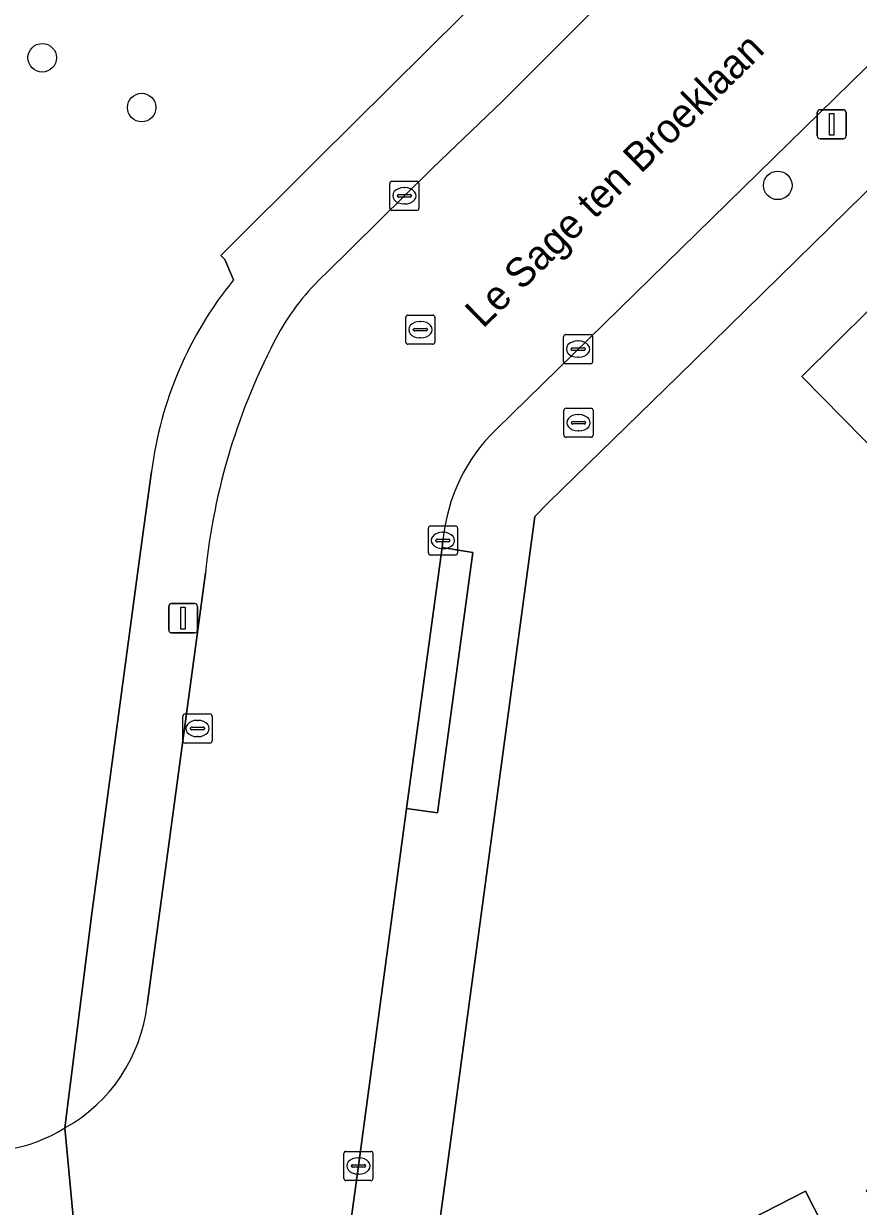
# Model space of a CAD drawing. Extents: x 161402 to 161933, y 381647 to 382315.
# Drawn here: x 161759.22 to 161787.85, y 382075.91 to 382116.47 of the extents above; entities that cross this region are included whole.
import ezdxf

# ---------------------------------------------------------------- set-up
doc = ezdxf.new("R2010")
doc.units = 0
for name, color, linetype in [('IMGEO_Boom', 7, 'Continuous'), ('IMGEO_Brandkraan', 7, 'Continuous'), ('IMGEO_Erf', 7, 'Continuous'), ('IMGEO_Groenvoorziening', 7, 'Continuous'), ('IMGEO_Kolk', 7, 'Continuous'), ('IMGEO_Lichtmast', 7, 'Continuous'), ('IMGEO_Muur', 7, 'Continuous'), ('IMGEO_Openbare_ruimte_label', 7, 'Continuous'), ('IMGEO_Pand', 7, 'Continuous'), ('IMGEO_Rijbaan_lokaal_gesloten', 7, 'Continuous'), ('IMGEO_Rioolput', 7, 'Continuous'), ('IMGEO_Voetpad_open', 7, 'Continuous')]:
    doc.layers.add(name, color=color, linetype=linetype)

msp = doc.modelspace()

# ---------------------------------------------------------------- linework, layer by layer
at = {"layer": 'IMGEO_Boom'}
for centre in [(161759.861, 382115.302), (161763.272, 382113.595), (161785.089, 382110.925)]:
    msp.add_circle(centre, 0.489, dxfattribs=at)
at = {"layer": 'IMGEO_Brandkraan'}
for p, q in [((161777.831, 382103.284), (161778.683, 382103.284)), ((161777.756, 382102.358), (161777.756, 382103.21)), ((161778.244, 382103.064), (161778.269, 382103.064)), ((161778.757, 382103.21), (161778.757, 382102.358)), ((161778.015, 382102.778), (161778.015, 382102.79)), ((161778.453, 382102.741), (161778.055, 382102.741)), ((161778.058, 382102.827), (161778.456, 382102.827)), ((161778.267, 382102.504), (161778.242, 382102.504)), ((161778.499, 382102.79), (161778.499, 382102.778)), ((161778.683, 382102.284), (161777.831, 382102.284))]:
    msp.add_line(p, q, dxfattribs=at)
for points in [[(161777.831, 382103.284), (161778.683, 382103.284)], [(161777.756, 382102.358), (161777.756, 382103.21)], [(161778.757, 382103.21), (161778.757, 382102.358)], [(161778.683, 382102.284), (161777.831, 382102.284)]]:
    msp.add_lwpolyline(points, dxfattribs=at)
for centre, radius, start, end in [((161777.833, 382103.208), 0.0765, 91.552, 178.448), ((161777.833, 382103.208), 0.0765, 91.552, 178.448), ((161778.681, 382103.208), 0.0765, 1.552, 88.448), ((161778.681, 382103.208), 0.0765, 1.552, 88.448), ((161778.055, 382102.787), 0.0403, 85.8775, 175.7526), ((161778.052, 382102.777), 0.0366, 178.938, 274.7102), ((161778.456, 382102.784), 0.043, 264.8664, 352.4533), ((161778.46, 382102.789), 0.0386, 1.7309, 96.639), ((161777.833, 382102.36), 0.0765, 181.552, 268.448), ((161777.833, 382102.36), 0.0765, 181.552, 268.448), ((161778.681, 382102.36), 0.0765, 271.552, 358.448), ((161778.681, 382102.36), 0.0765, 271.552, 358.448)]:
    msp.add_arc(centre, radius, start, end, dxfattribs=at)
for centre, major_axis, ratio, start_param, end_param in [((161778.243, 382102.784), (-0.387, 0.002), 0.722429, 4.712389, 7.853982), ((161778.268, 382102.784), (-0.39, 0.002), 0.717154, 1.570796, 4.712389)]:
    msp.add_ellipse(centre, major_axis=major_axis, ratio=ratio, start_param=start_param, end_param=end_param, dxfattribs=at)
at = {"layer": 'IMGEO_Erf'}
for points in [[(161804.249, 382126.529), (161781.67, 382104.382), (161777.238, 382100.058), (161776.756, 382099.569), (161773.703, 382076.916), (161762.821, 381997.456)], [(161789.417, 382100.81), (161785.909, 382104.373), (161789.402, 382107.818)], [(161783.505, 382056.018), (161783.263, 382058.701), (161776.645, 382071.618), (161786.037, 382076.43), (161787.222, 382074.116), (161788.878, 382075.604), (161788.117, 382076.444), (161788.484, 382076.777), (161796.387, 382068.043), (161796.339, 382068), (161797.532, 382065.679), (161799.064, 382066.435), (161805.902, 382053.086)]]:
    msp.add_lwpolyline(points, dxfattribs=at)
at = {"layer": 'IMGEO_Groenvoorziening'}
for points in [[(161766.425, 382107.684), (161766.123, 382108.385), (161765.984, 382108.524), (161769.279, 382111.799), (161779.35, 382121.795), (161765.481, 382129.756), (161763.216, 382125.122), (161761.867, 382126.157)], [(161760.641, 382078.597), (161761.566, 382085.949), (161763.229, 382098.37), (161763.613, 382101.111)]]:
    msp.add_lwpolyline(points, dxfattribs=at)
for centre, radius, start, end in [((161776.479, 382099.495), 12.967, 140.8362, 172.8403), ((161757.811, 382083.138), 5.351, 257.0565, 301.9373)]:
    msp.add_arc(centre, radius, start, end, dxfattribs=at)
at = {"layer": 'IMGEO_Kolk'}
for p, q in [((161771.782, 382110.142), (161771.782, 382110.994)), ((161771.857, 382111.068), (161772.709, 382111.068)), ((161772.783, 382110.994), (161772.783, 382110.142)), ((161772.041, 382110.562), (161772.041, 382110.574)), ((161772.084, 382110.611), (161772.482, 382110.611)), ((161772.27, 382110.848), (161772.295, 382110.848)), ((161772.525, 382110.574), (161772.525, 382110.562)), ((161772.479, 382110.525), (161772.081, 382110.525)), ((161772.293, 382110.288), (161772.268, 382110.288)), ((161772.709, 382110.068), (161771.857, 382110.068)), ((161777.739, 382104.884), (161777.739, 382105.736)), ((161777.814, 382105.81), (161778.666, 382105.81)), ((161778.74, 382105.736), (161778.74, 382104.884)), ((161777.998, 382105.304), (161777.998, 382105.316)), ((161778.041, 382105.353), (161778.439, 382105.353)), ((161778.227, 382105.59), (161778.252, 382105.59)), ((161778.482, 382105.316), (161778.482, 382105.304)), ((161778.436, 382105.267), (161778.038, 382105.267)), ((161778.25, 382105.03), (161778.225, 382105.03)), ((161778.666, 382104.81), (161777.814, 382104.81)), ((161773.179, 382099.246), (161774.031, 382099.246)), ((161773.104, 382098.32), (161773.104, 382099.172)), ((161773.406, 382098.789), (161773.804, 382098.789)), ((161773.592, 382099.026), (161773.617, 382099.026)), ((161774.105, 382099.172), (161774.105, 382098.32)), ((161773.363, 382098.74), (161773.363, 382098.752)), ((161773.801, 382098.703), (161773.403, 382098.703)), ((161773.615, 382098.466), (161773.59, 382098.466)), ((161773.847, 382098.752), (161773.847, 382098.74)), ((161774.031, 382098.246), (161773.179, 382098.246)), ((161764.687, 382091.871), (161764.687, 382092.723)), ((161764.762, 382092.797), (161765.614, 382092.797)), ((161765.688, 382092.723), (161765.688, 382091.871)), ((161764.946, 382092.291), (161764.946, 382092.303)), ((161764.989, 382092.34), (161765.387, 382092.34)), ((161765.175, 382092.577), (161765.2, 382092.577)), ((161765.43, 382092.303), (161765.43, 382092.291)), ((161765.384, 382092.254), (161764.986, 382092.254)), ((161765.198, 382092.017), (161765.173, 382092.017)), ((161765.614, 382091.797), (161764.762, 382091.797)), ((161770.205, 382076.868), (161770.205, 382077.72)), ((161770.28, 382077.794), (161771.132, 382077.794)), ((161771.206, 382077.72), (161771.206, 382076.868)), ((161770.464, 382077.288), (161770.464, 382077.3)), ((161770.507, 382077.337), (161770.905, 382077.337)), ((161770.693, 382077.574), (161770.718, 382077.574)), ((161770.948, 382077.3), (161770.948, 382077.288)), ((161770.902, 382077.251), (161770.504, 382077.251)), ((161770.716, 382077.014), (161770.691, 382077.014)), ((161771.132, 382076.794), (161770.28, 382076.794))]:
    msp.add_line(p, q, dxfattribs=at)
for points in [[(161771.782, 382110.142), (161771.782, 382110.994)], [(161771.857, 382111.068), (161772.709, 382111.068)], [(161772.783, 382110.994), (161772.783, 382110.142)], [(161772.709, 382110.068), (161771.857, 382110.068)], [(161777.739, 382104.884), (161777.739, 382105.736)], [(161777.814, 382105.81), (161778.666, 382105.81)], [(161778.74, 382105.736), (161778.74, 382104.884)], [(161778.666, 382104.81), (161777.814, 382104.81)], [(161773.179, 382099.246), (161774.031, 382099.246)], [(161773.104, 382098.32), (161773.104, 382099.172)], [(161774.105, 382099.172), (161774.105, 382098.32)], [(161774.031, 382098.246), (161773.179, 382098.246)], [(161764.687, 382091.871), (161764.687, 382092.723)], [(161764.762, 382092.797), (161765.614, 382092.797)], [(161765.688, 382092.723), (161765.688, 382091.871)], [(161765.614, 382091.797), (161764.762, 382091.797)], [(161770.205, 382076.868), (161770.205, 382077.72)], [(161770.28, 382077.794), (161771.132, 382077.794)], [(161771.206, 382077.72), (161771.206, 382076.868)], [(161771.132, 382076.794), (161770.28, 382076.794)]]:
    msp.add_lwpolyline(points, dxfattribs=at)
for centre, radius, start, end in [((161771.859, 382110.992), 0.0765, 91.552, 178.448), ((161771.859, 382110.992), 0.0765, 91.552, 178.448), ((161772.707, 382110.992), 0.0765, 1.552, 88.448), ((161772.707, 382110.992), 0.0765, 1.552, 88.448), ((161772.081, 382110.571), 0.0403, 85.8775, 175.7526), ((161772.078, 382110.561), 0.0366, 178.938, 274.7102), ((161772.482, 382110.568), 0.043, 264.8664, 352.4533), ((161772.486, 382110.573), 0.0386, 1.7309, 96.639), ((161771.859, 382110.144), 0.0765, 181.552, 268.448), ((161771.859, 382110.144), 0.0765, 181.552, 268.448), ((161772.707, 382110.144), 0.0765, 271.552, 358.448), ((161772.707, 382110.144), 0.0765, 271.552, 358.448), ((161777.816, 382105.734), 0.0765, 91.552, 178.448), ((161777.816, 382105.734), 0.0765, 91.552, 178.448), ((161778.664, 382105.734), 0.0765, 1.552, 88.448), ((161778.664, 382105.734), 0.0765, 1.552, 88.448), ((161778.038, 382105.313), 0.0403, 85.8775, 175.7526), ((161778.035, 382105.303), 0.0366, 178.938, 274.7102), ((161778.439, 382105.31), 0.043, 264.8664, 352.4533), ((161778.443, 382105.315), 0.0386, 1.7309, 96.639), ((161777.816, 382104.886), 0.0765, 181.552, 268.448), ((161777.816, 382104.886), 0.0765, 181.552, 268.448), ((161778.664, 382104.886), 0.0765, 271.552, 358.448), ((161778.664, 382104.886), 0.0765, 271.552, 358.448), ((161773.181, 382099.17), 0.0765, 91.552, 178.448), ((161773.181, 382099.17), 0.0765, 91.552, 178.448), ((161774.029, 382099.17), 0.0765, 1.552, 88.448), ((161774.029, 382099.17), 0.0765, 1.552, 88.448), ((161773.403, 382098.749), 0.0403, 85.8775, 175.7526), ((161773.808, 382098.751), 0.0386, 1.7309, 96.639), ((161773.4, 382098.739), 0.0366, 178.938, 274.7102), ((161773.804, 382098.746), 0.043, 264.8664, 352.4533), ((161773.181, 382098.322), 0.0765, 181.552, 268.448), ((161773.181, 382098.322), 0.0765, 181.552, 268.448), ((161774.029, 382098.322), 0.0765, 271.552, 358.448), ((161774.029, 382098.322), 0.0765, 271.552, 358.448), ((161764.764, 382092.721), 0.0765, 91.552, 178.448), ((161764.764, 382092.721), 0.0765, 91.552, 178.448), ((161765.612, 382092.721), 0.0765, 1.552, 88.448), ((161765.612, 382092.721), 0.0765, 1.552, 88.448), ((161764.986, 382092.3), 0.0403, 85.8775, 175.7526), ((161765.391, 382092.302), 0.0386, 1.7309, 96.639), ((161764.983, 382092.29), 0.0366, 178.938, 274.7102), ((161765.387, 382092.297), 0.043, 264.8664, 352.4533), ((161764.764, 382091.873), 0.0765, 181.552, 268.448), ((161764.764, 382091.873), 0.0765, 181.552, 268.448), ((161765.612, 382091.873), 0.0765, 271.552, 358.448), ((161765.612, 382091.873), 0.0765, 271.552, 358.448), ((161770.282, 382077.718), 0.0765, 91.552, 178.448), ((161770.282, 382077.718), 0.0765, 91.552, 178.448), ((161771.13, 382077.718), 0.0765, 1.552, 88.448), ((161771.13, 382077.718), 0.0765, 1.552, 88.448), ((161770.504, 382077.297), 0.0403, 85.8775, 175.7526), ((161770.501, 382077.287), 0.0366, 178.938, 274.7102), ((161770.905, 382077.294), 0.043, 264.8664, 352.4533), ((161770.909, 382077.299), 0.0386, 1.7309, 96.639), ((161770.282, 382076.87), 0.0765, 181.552, 268.448), ((161770.282, 382076.87), 0.0765, 181.552, 268.448), ((161771.13, 382076.87), 0.0765, 271.552, 358.448), ((161771.13, 382076.87), 0.0765, 271.552, 358.448)]:
    msp.add_arc(centre, radius, start, end, dxfattribs=at)
for centre, major_axis, ratio, start_param, end_param in [((161772.269, 382110.568), (-0.387, 0.002), 0.722429, 4.712389, 7.853982), ((161772.294, 382110.568), (-0.39, 0.002), 0.717154, 1.570796, 4.712389), ((161778.226, 382105.31), (-0.387, 0.002), 0.722429, 4.712389, 7.853982), ((161778.251, 382105.31), (-0.39, 0.002), 0.717154, 1.570796, 4.712389), ((161773.591, 382098.746), (-0.387, 0.002), 0.722429, 4.712389, 7.853982), ((161773.616, 382098.746), (-0.39, 0.002), 0.717154, 1.570796, 4.712389), ((161765.174, 382092.297), (-0.387, 0.002), 0.722429, 4.712389, 7.853982), ((161765.199, 382092.297), (-0.39, 0.002), 0.717154, 1.570796, 4.712389), ((161770.692, 382077.294), (-0.387, 0.002), 0.722429, 4.712389, 7.853982), ((161770.717, 382077.294), (-0.39, 0.002), 0.717154, 1.570796, 4.712389)]:
    msp.add_ellipse(centre, major_axis=major_axis, ratio=ratio, start_param=start_param, end_param=end_param, dxfattribs=at)
at = {"layer": 'IMGEO_Lichtmast'}
for p, q in [((161786.44, 382112.621), (161786.44, 382113.421)), ((161786.44, 382113.421), (161786.44, 382112.621)), ((161786.54, 382113.521), (161787.33, 382113.521)), ((161787.33, 382113.521), (161786.54, 382113.521)), ((161787.43, 382113.421), (161787.43, 382112.621)), ((161787.43, 382112.621), (161787.43, 382113.421)), ((161787.33, 382112.521), (161786.54, 382112.521)), ((161786.54, 382112.521), (161787.33, 382112.521)), ((161764.199, 382095.679), (161764.199, 382096.479)), ((161764.199, 382096.479), (161764.199, 382095.679)), ((161764.299, 382096.579), (161765.089, 382096.579)), ((161765.089, 382096.579), (161764.299, 382096.579)), ((161765.189, 382096.479), (161765.189, 382095.679)), ((161765.189, 382095.679), (161765.189, 382096.479)), ((161765.089, 382095.579), (161764.299, 382095.579)), ((161764.299, 382095.579), (161765.089, 382095.579))]:
    msp.add_line(p, q, dxfattribs=at)
for points in [[(161786.86, 382113.396), (161787.01, 382113.396), (161787.01, 382112.646), (161786.86, 382112.646), (161786.86, 382113.396)], [(161764.619, 382096.454), (161764.769, 382096.454), (161764.769, 382095.704), (161764.619, 382095.704), (161764.619, 382096.454)]]:
    msp.add_lwpolyline(points, dxfattribs=at)
for centre, start, end in [((161786.54, 382113.421), 90, 180), ((161786.54, 382113.421), 90, 180), ((161787.33, 382113.421), 0, 90), ((161787.33, 382113.421), 360, 90), ((161786.54, 382112.621), 180, 270), ((161786.54, 382112.621), 180, 270), ((161787.33, 382112.621), 270, 0), ((161787.33, 382112.621), 270, 0), ((161764.299, 382096.479), 90, 180), ((161764.299, 382096.479), 90, 180), ((161765.089, 382096.479), 0, 90), ((161765.089, 382096.479), 360, 90), ((161764.299, 382095.679), 180, 270), ((161764.299, 382095.679), 180, 270), ((161765.089, 382095.679), 270, 0), ((161765.089, 382095.679), 270, 0)]:
    msp.add_arc(centre, 0.1, start, end, dxfattribs=at)
at = {"layer": 'IMGEO_Muur'}
for points in [[(161769.279, 382111.799), (161765.984, 382108.524), (161766.123, 382108.385), (161766.425, 382107.684)], [(161763.613, 382101.111), (161763.229, 382098.37)]]:
    msp.add_lwpolyline(points, dxfattribs=at)
msp.add_arc((161776.479, 382099.495), 12.967, 140.8362, 172.8403, dxfattribs=at)
at = {"layer": 'IMGEO_Pand'}
for points in [[(161789.402, 382107.818), (161785.909, 382104.373), (161789.417, 382100.81)], [(161796.339, 382068), (161796.387, 382068.043), (161788.484, 382076.777), (161788.117, 382076.444), (161788.878, 382075.604), (161787.222, 382074.116), (161786.037, 382076.43), (161776.645, 382071.618), (161783.263, 382058.701), (161783.505, 382056.018)]]:
    msp.add_lwpolyline(points, dxfattribs=at)
at = {"layer": 'IMGEO_Rijbaan_lokaal_gesloten'}
for points in [[(161810.829, 382138.748), (161811.571, 382137.928), (161813.317, 382139.636), (161807.63, 382145.403), (161806.285, 382144.085), (161803.661, 382141.516), (161803.248, 382141.112), (161795.969, 382134.059), (161790.782, 382128.901), (161787.157, 382125.329), (161786.084, 382124.255), (161775.652, 382113.816), (161773.249, 382111.52), (161769.574, 382107.889)], [(161775.438, 382102.569), (161800.253, 382126.852)], [(161760.641, 382078.597), (161761.399, 382070.432), (161769.695, 382069.904), (161770.706, 382077.294), (161772.36, 382089.55), (161773.576, 382098.504), (161773.605, 382098.746)], [(161765.459, 382097.622), (161763.588, 382083.758), (161763.457, 382082.821)], [(161723.499, 382081.074), (161725.039, 382080.585), (161727.317, 382079.877), (161729.208, 382079.301), (161731.057, 382078.758), (161732.976, 382078.22), (161743.495, 382075.362), (161755.857, 382072.012), (161755.957, 382071.985), (161756.821, 382071.728), (161761.399, 382070.432), (161760.641, 382078.597)]]:
    msp.add_lwpolyline(points, dxfattribs=at)
for centre, radius, start, end in [((161775.26, 382101.771), 8.353, 132.9056, 151.1279), ((161787.37, 382095.431), 22.021, 151.8964, 174.2893), ((161779.701, 382098.174), 6.123, 134.1264, 174.6413), ((161757.95, 382083.441), 5.542, 299.0484, 353.5715), ((161757.811, 382083.138), 5.351, 257.0565, 301.9373)]:
    msp.add_arc(centre, radius, start, end, dxfattribs=at)
at = {"layer": 'IMGEO_Rioolput'}
for p, q in [((161772.33, 382105.551), (161772.33, 382106.403)), ((161772.405, 382106.477), (161773.257, 382106.477)), ((161772.818, 382106.257), (161772.843, 382106.257)), ((161773.331, 382106.403), (161773.331, 382105.551)), ((161772.589, 382105.971), (161772.589, 382105.983)), ((161773.027, 382105.934), (161772.629, 382105.934)), ((161772.632, 382106.02), (161773.03, 382106.02)), ((161772.841, 382105.697), (161772.816, 382105.697)), ((161773.073, 382105.983), (161773.073, 382105.971)), ((161773.257, 382105.477), (161772.405, 382105.477))]:
    msp.add_line(p, q, dxfattribs=at)
for points in [[(161772.33, 382105.551), (161772.33, 382106.403)], [(161772.405, 382106.477), (161773.257, 382106.477)], [(161773.331, 382106.403), (161773.331, 382105.551)], [(161773.257, 382105.477), (161772.405, 382105.477)]]:
    msp.add_lwpolyline(points, dxfattribs=at)
for centre, radius, start, end in [((161772.407, 382106.401), 0.0765, 91.552, 178.448), ((161772.407, 382106.401), 0.0765, 91.552, 178.448), ((161773.255, 382106.401), 0.0765, 1.552, 88.448), ((161773.255, 382106.401), 0.0765, 1.552, 88.448), ((161772.629, 382105.98), 0.0403, 85.8775, 175.7526), ((161772.626, 382105.97), 0.0366, 178.938, 274.7102), ((161773.03, 382105.977), 0.043, 264.8664, 352.4533), ((161773.034, 382105.982), 0.0386, 1.7309, 96.639), ((161772.407, 382105.553), 0.0765, 181.552, 268.448), ((161772.407, 382105.553), 0.0765, 181.552, 268.448), ((161773.255, 382105.553), 0.0765, 271.552, 358.448), ((161773.255, 382105.553), 0.0765, 271.552, 358.448)]:
    msp.add_arc(centre, radius, start, end, dxfattribs=at)
for centre, major_axis, ratio, start_param, end_param in [((161772.817, 382105.977), (-0.387, 0.002), 0.722429, 4.712389, 7.853982), ((161772.842, 382105.977), (-0.39, 0.002), 0.717154, 1.570796, 4.712389)]:
    msp.add_ellipse(centre, major_axis=major_axis, ratio=ratio, start_param=start_param, end_param=end_param, dxfattribs=at)
at = {"layer": 'IMGEO_Voetpad_open'}
for points in [[(161761.87, 381990.395), (161762.821, 381997.456), (161773.703, 382076.916), (161776.756, 382099.569), (161777.238, 382100.058), (161781.67, 382104.382), (161804.249, 382126.529), (161826.48, 382148.395), (161845.138, 382166.658), (161857.746, 382179.014)], [(161807.598, 382135.507), (161808.326, 382134.752), (161805.139, 382131.633), (161802.994, 382129.534), (161803.304, 382129.202), (161800.583, 382126.535), (161800.253, 382126.852), (161775.438, 382102.569)], [(161786.084, 382124.255), (161784.015, 382126.305), (161781.022, 382124.329), (161779.35, 382121.795), (161769.279, 382111.799), (161765.984, 382108.524), (161766.123, 382108.385), (161766.425, 382107.684)], [(161769.574, 382107.889), (161773.249, 382111.52), (161775.652, 382113.816), (161786.084, 382124.255)], [(161763.613, 382101.111), (161763.229, 382098.37), (161761.566, 382085.949), (161760.641, 382078.597)], [(161773.605, 382098.746), (161773.576, 382098.504), (161774.632, 382098.337), (161773.418, 382089.408), (161772.36, 382089.55), (161770.706, 382077.294), (161769.695, 382069.904), (161759.969, 381998.846), (161759.49, 381995.39), (161759.283, 381993.653)], [(161763.457, 382082.821), (161763.588, 382083.758), (161765.459, 382097.622)]]:
    msp.add_lwpolyline(points, dxfattribs=at)
msp.add_lwpolyline([(161773.576, 382098.504), (161772.36, 382089.55), (161773.418, 382089.408), (161774.632, 382098.337)], close=True, dxfattribs=at)
for centre, radius, start, end in [((161775.26, 382101.771), 8.353, 132.9056, 151.1279), ((161776.479, 382099.495), 12.967, 140.8362, 172.8403), ((161787.37, 382095.431), 22.021, 151.8964, 174.2893), ((161779.701, 382098.174), 6.123, 134.1264, 174.6413), ((161757.95, 382083.441), 5.542, 299.0484, 353.5715)]:
    msp.add_arc(centre, radius, start, end, dxfattribs=at)

# ---------------------------------------------------------------- texts
at = {"layer": 'IMGEO_Openbare_ruimte_label'}
msp.add_text('Le Sage ten Broeklaan', height=1, rotation=44.4327, dxfattribs=at).set_placement((161774.976, 382105.992))

doc.saveas('drawing.dxf')
